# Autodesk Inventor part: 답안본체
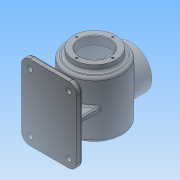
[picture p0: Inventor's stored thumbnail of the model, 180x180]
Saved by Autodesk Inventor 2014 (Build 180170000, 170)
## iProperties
Created: 2016-09
Part Number: 답안본체
Material: 일반
Document SubType Name: 판금
Designer: net
Density: 1 g/cm^3
Sheet Metal Rule: 기본값
Appearance: 기본값
Author: net
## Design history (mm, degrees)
sketch "스케치3"
  geometry: L1 (0, 0)-(38, 0); L2 (0, -122)-(0, 0); L3 (38, 0)-(38, -12); L4 (38, -12)-(50, -12); L5 (50, -12)-(50, -112); A1 r 115 centre (3.008, -7.039) between (0, -122) and (50, -112)
  constraints: 10 end point, 2 parallel, 2 point on circle, 1 centre point, 1 horizontal, 1 perpendicular
  dimensions: "d18" = 122 distance from line of L2.start L1; "d24" = 100 diameter of L5 L2; "d25" = 76 diameter of L3 L2; "d26" = 122 distance of L2.start L1.start; "d30" = 110 distance from line of L4 L2.start; "d31" = 115 radius of A1; "d33" = 100 distance of L4.end L5.end
revolve "회전1" sketch "스케치3" stored, may be unused: angle "d27" = 90 deg
fillet "모깎기1" dims "d28" = 5
sketch "스케치4"
  geometry: 1 further point
node "작업 평면1"
node "작업 평면3"
  node "작업 평면2"
sketch "스케치6"
  geometry: L1 (-50, -72)-(50, -72); L2 (50, -72)-(50, -82); L3 (50, -82)-(-50, -82); L4 (-50, -82)-(-50, -72); L5 (0, 0)-(0, -82); 1 further point
  constraints: 10 end point, 2 midpoint, 2 parallel, 2 perpendicular, 1 horizontal, 1 point on line
  dimensions: "d43" = 10 distance of L1.end L2.end; "d44" = 100 distance of L2.end L3.end; "d81" = 82 distance from line of L3 L5.start
extrude "돌출2" join sketch "스케치6" distance "d46" = 135; taper "d47" = 0 deg
fillet "모깎기4" dims "d48" = 15
fillet "모깎기5" dims "d49" = 3
hole "구멍1" diameter "d52" = 10; stored, may be unused: countersink angle "d56" = 90 deg, drill point angle "d58" = 118 deg; dims "d50" = 10, "d51" = 10, "d53" = 6, "d54" = 4, "d55" = 2, "d57" = 0.5 (derived)
sketch "스케치8"
  geometry: L1 (0, 0)-(70, 0) reference; L2 (-12, -117)-(-12, -12) reference; L3 (70, -129)-(0, -129) reference; L4 (82, -12)-(82, -117) reference; L5 (30, -24.5)-(40, -24.5); L6 (40, -24.5)-(40, -104.5); L7 (40, -104.5)-(30, -104.5); L8 (30, -104.5)-(30, -24.5); L9 (-12, -64.5)-(82, -64.5); L10 (35, 0)-(35, -129); 1 further point
  constraints: 12 end point, 4 midpoint, 2 parallel, 1 horizontal, 1 perpendicular
  dimensions: "d59" = 40 distance between parallel lines of L9 L5; "d60" = 40 distance between parallel lines of L7 L9; "d61" = 10 distance between parallel lines of L6 L8; "d62" = 5 distance between parallel lines of L10 L8
extrude "돌출3" join sketch "스케치8" distance "d63" = 100; taper "d64" = 0 deg
feature "면 기울기1" dims angle "d65" = 5 deg
feature "면 기울기2" dims angle "d66" = 5 deg
node "작업 평면4"
sketch "스케치9"
  geometry: L1 (-40, -16.712)-(40, -16.712); L2 (40, -16.712)-(40, -72); L3 (40, -72)-(-40, -72); L4 (-40, -72)-(-40, -16.712); L5 (-35, -72)-(35, -72) reference; C1 r 50 at (0, 0) reference; 1 further point
  constraints: 8 end point, 2 parallel, 1 horizontal, 1 perpendicular
  dimensions: "d67" = 0 distance between parallel lines of L5 L3; "d68" = 40 distance from line of point (0, 0) L4; "d69" = 40 distance from line of L2 point (0, 0); "d70" = 55.28833 distance between parallel lines of L3 L1
extrude "돌출4" join sketch "스케치9" stored distance "d71" = 10; taper "d72" = 0 deg
node "작업 평면5"
sketch "스케치10"
  geometry: L1 (85, -22.5)-(-15, -22.5) reference; L2 (81.909, -118.83)-(-11.909, -118.83) reference; L3 (35, -22.5)-(35, -118.83); L4 (-10, -17.5)-(80, -17.5) reference; C1 r 38 at (35, -67.5); 1 further point
  constraints: 2 end point, 2 midpoint, 1 centre point, 1 point on line
  dimensions: "d77" = 76 diameter of C1; "d78" = 50 distance from line of L4 C1.centre
extrude "돌출5" join sketch "스케치10" stored distance "d79" = 10; taper "d80" = 0 deg
fillet "모깎기7" dims "d82" = 3
node "작업 평면6"
sketch "스케치15" dims "d86" = 65
  geometry: L1 (0, 0)-(0, 32.5); C1 r 38 at (0, 0) reference; 2 further points
  constraints: 2 coincident, 2 end point, 1 vertical, 1 vertical alignment, 2 other
hole "구멍2" sketch "스케치15" at (0, 32.5) diameter "d87" = 4; stored, may be unused: countersink angle "d91" = 90 deg, drill point angle "d93" = 118 deg; dims "d88" = 6, "d89" = 4, "d90" = 2, "d92" = 10
feature "스레드1" dims "d94" = 8, "d95" = 0
sketch "스케치16" dims "d99" = 65
  geometry: L1 (0, 0)-(0, 32.5); C1 r 38 at (0, 0) reference; 1 further point
  constraints: 2 coincident, 2 end point, 1 vertical, 1 vertical alignment, 2 other
hole "구멍3" sketch "스케치16" at (0, 32.5) diameter "d100" = 4; stored, may be unused: countersink angle "d104" = 90 deg, drill point angle "d106" = 118 deg; dims "d101" = 6, "d102" = 4, "d103" = 2, "d105" = 10
feature "스레드2" dims "d107" = 8, "d108" = 0
node "작업 평면7"
sketch "스케치18"
  geometry: C1 r 38 at (0, 0) reference; C2 r 27 at (0, 0)
  constraints: 1 centre point, 1 coincident
  dimensions: "d119" = 54 diameter of C2
extrude "돌출6" cut sketch "스케치18" distance "d120" = 15; taper "d121" = 0 deg
sketch "스케치20"
  geometry: C1 r 38 at (0, 0) reference; C2 r 27 at (0, 0); 1 further point
  constraints: 1 centre point, 1 coincident
  dimensions: "d122" = 54 diameter of C2
extrude "돌출7" cut sketch "스케치20" distance "d123" = 50; taper "d124" = 0 deg
node "작업 평면8"
sketch "스케치21"
  geometry: C1 r 47 at (0, 0); 1 further point
  constraints: 1 centre point, 1 coincident
  dimensions: "d126" = 94 diameter of C1
extrude "돌출8" cut sketch "스케치21" stored distance "d127" = 94; taper "d128" = 0 deg
sketch "스케치22"
  geometry: 1 further point
sketch "스케치23"
  geometry: L1 (46.909, -113.33)-(-46.909, -113.33) reference; L2 (-47, -109)-(47, -109) reference; L3 (0, -122)-(0, -109); L4 (0, -119.163)-(0, -109); L5 (47, -109)-(0, -109); A1 r 115 centre (3.008, -7.039) between (3.008, -122.039) and (46.909, -113.33) reference; A2 r 5 centre (45, -108.709) between (46.909, -113.33) and (50, -108.709) reference; A3 r 112 centre (0.38, -7.164) between (0, -119.163) and (47, -109); 1 further point
  constraints: 6 end point, 2 collinear, 2 point on circle, 1 centre point, 1 midpoint, 1 point on line
  dimensions: "d129" = 112 radius of A3; "d130" = 0.12463 vertical distance of A1.centre A3.centre
revolve "회전2" sketch "스케치23" stored, may be unused: angle "d131" = 90 deg
fillet "모깎기8" dims "d132" = 2
chamfer "모따기1" distance "d133" = 1; stored, may be unused: second distance "d134" = 2, angle "d135" = 45 deg
chamfer "모따기2" distance "d136" = 1; stored, may be unused: second distance "d137" = 2, angle "d138" = 45 deg
fillet "모깎기9" dims "d139" = 3, "d140" = 3
fillet "모깎기10" dims "d141" = 3
node "솔리드1"
mirror "대칭1"
mirror "대칭2"
pattern_circular "원형 패턴1" dims angle "d97" = 360 deg
pattern_circular "원형 패턴2" dims angle "d110" = 360 deg
node "투영된 루프1"
other parameters: "K계수" = 4.4, "BendRadius" = 0.5 (derived), "BendReliefWidth" = 0.5 (derived), "BendReliefDepth" = 0.25 (derived), "CornerReliefSize" = 2 (derived), "SeamGap" = 0.01, "MinimumRemnant" = 1 (derived), "TransitionRadius" = 0.5 (= BendRadius), "d34" = -82, "d42" = 67.5, "d76" = -147, "d85" = -122
